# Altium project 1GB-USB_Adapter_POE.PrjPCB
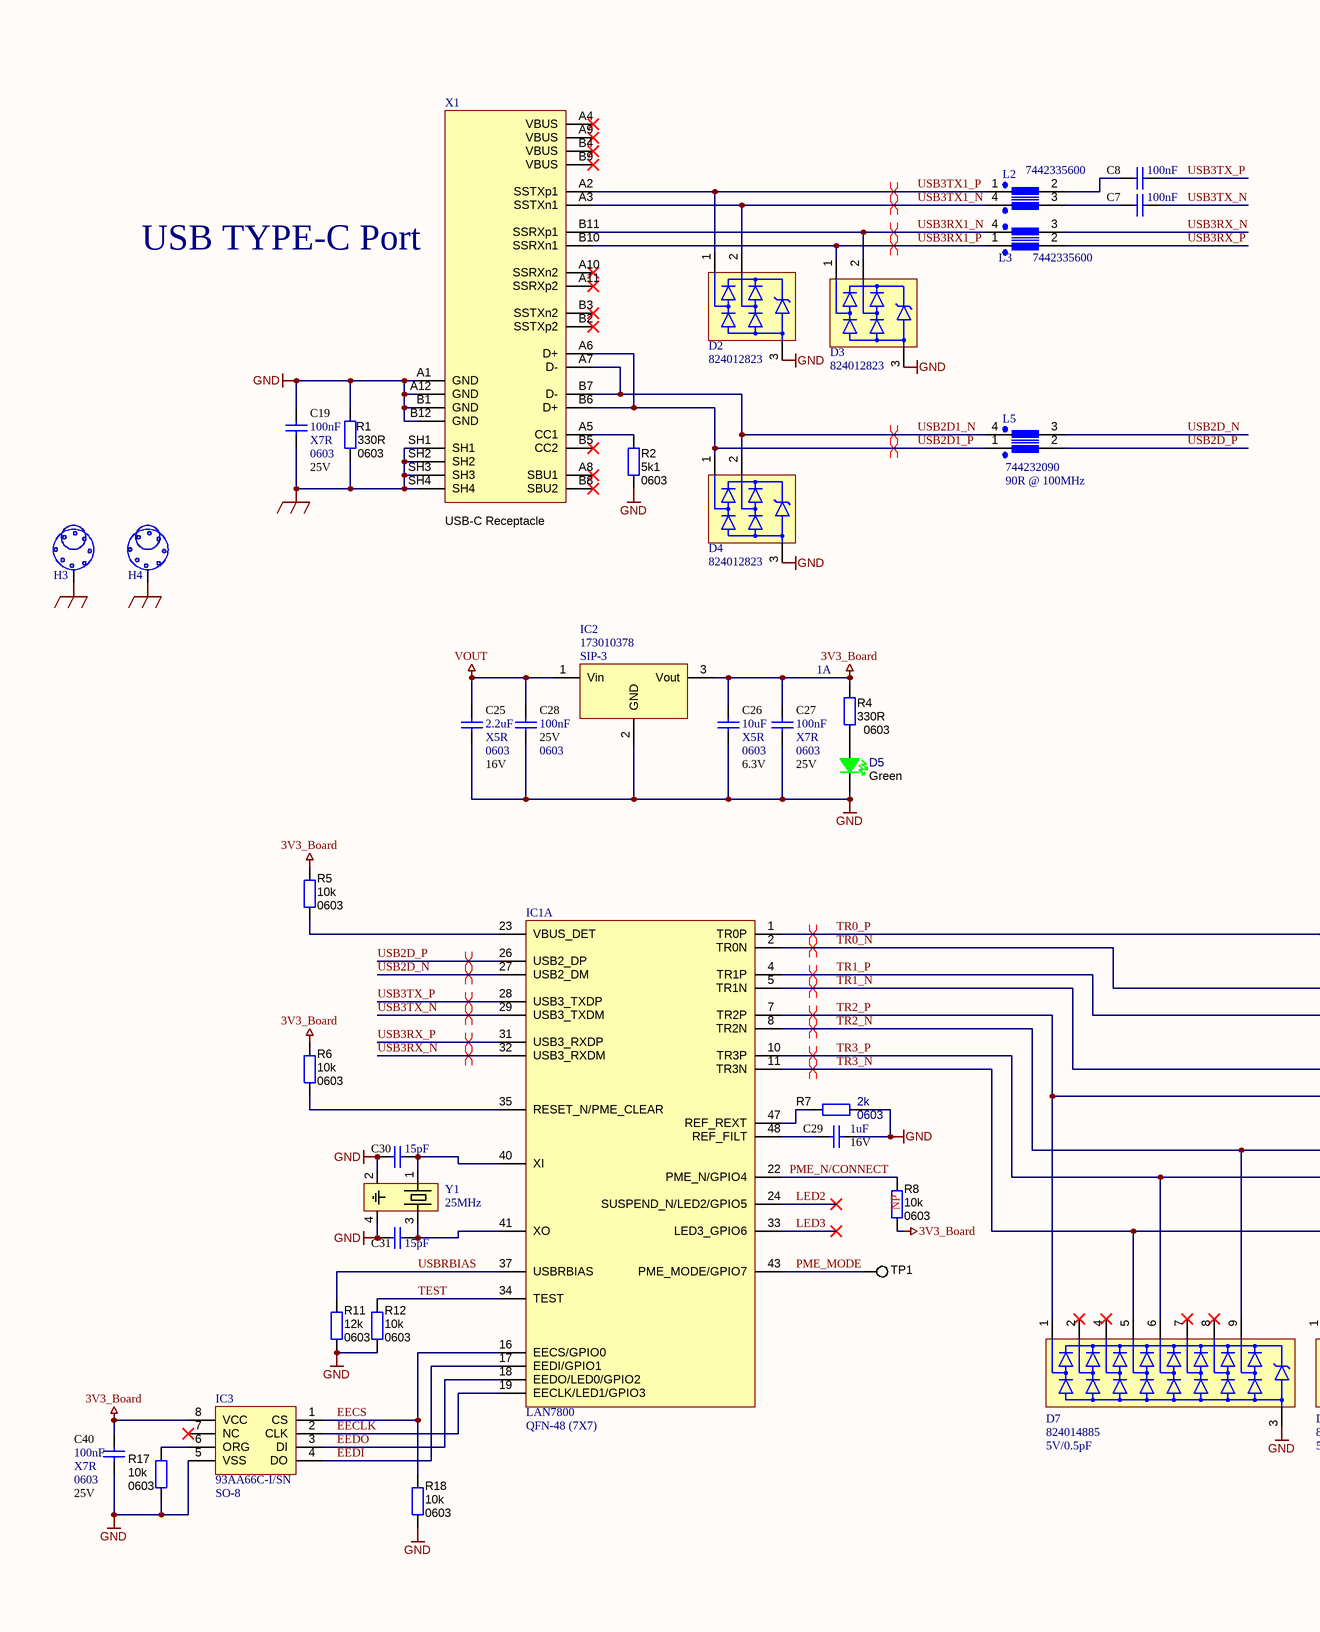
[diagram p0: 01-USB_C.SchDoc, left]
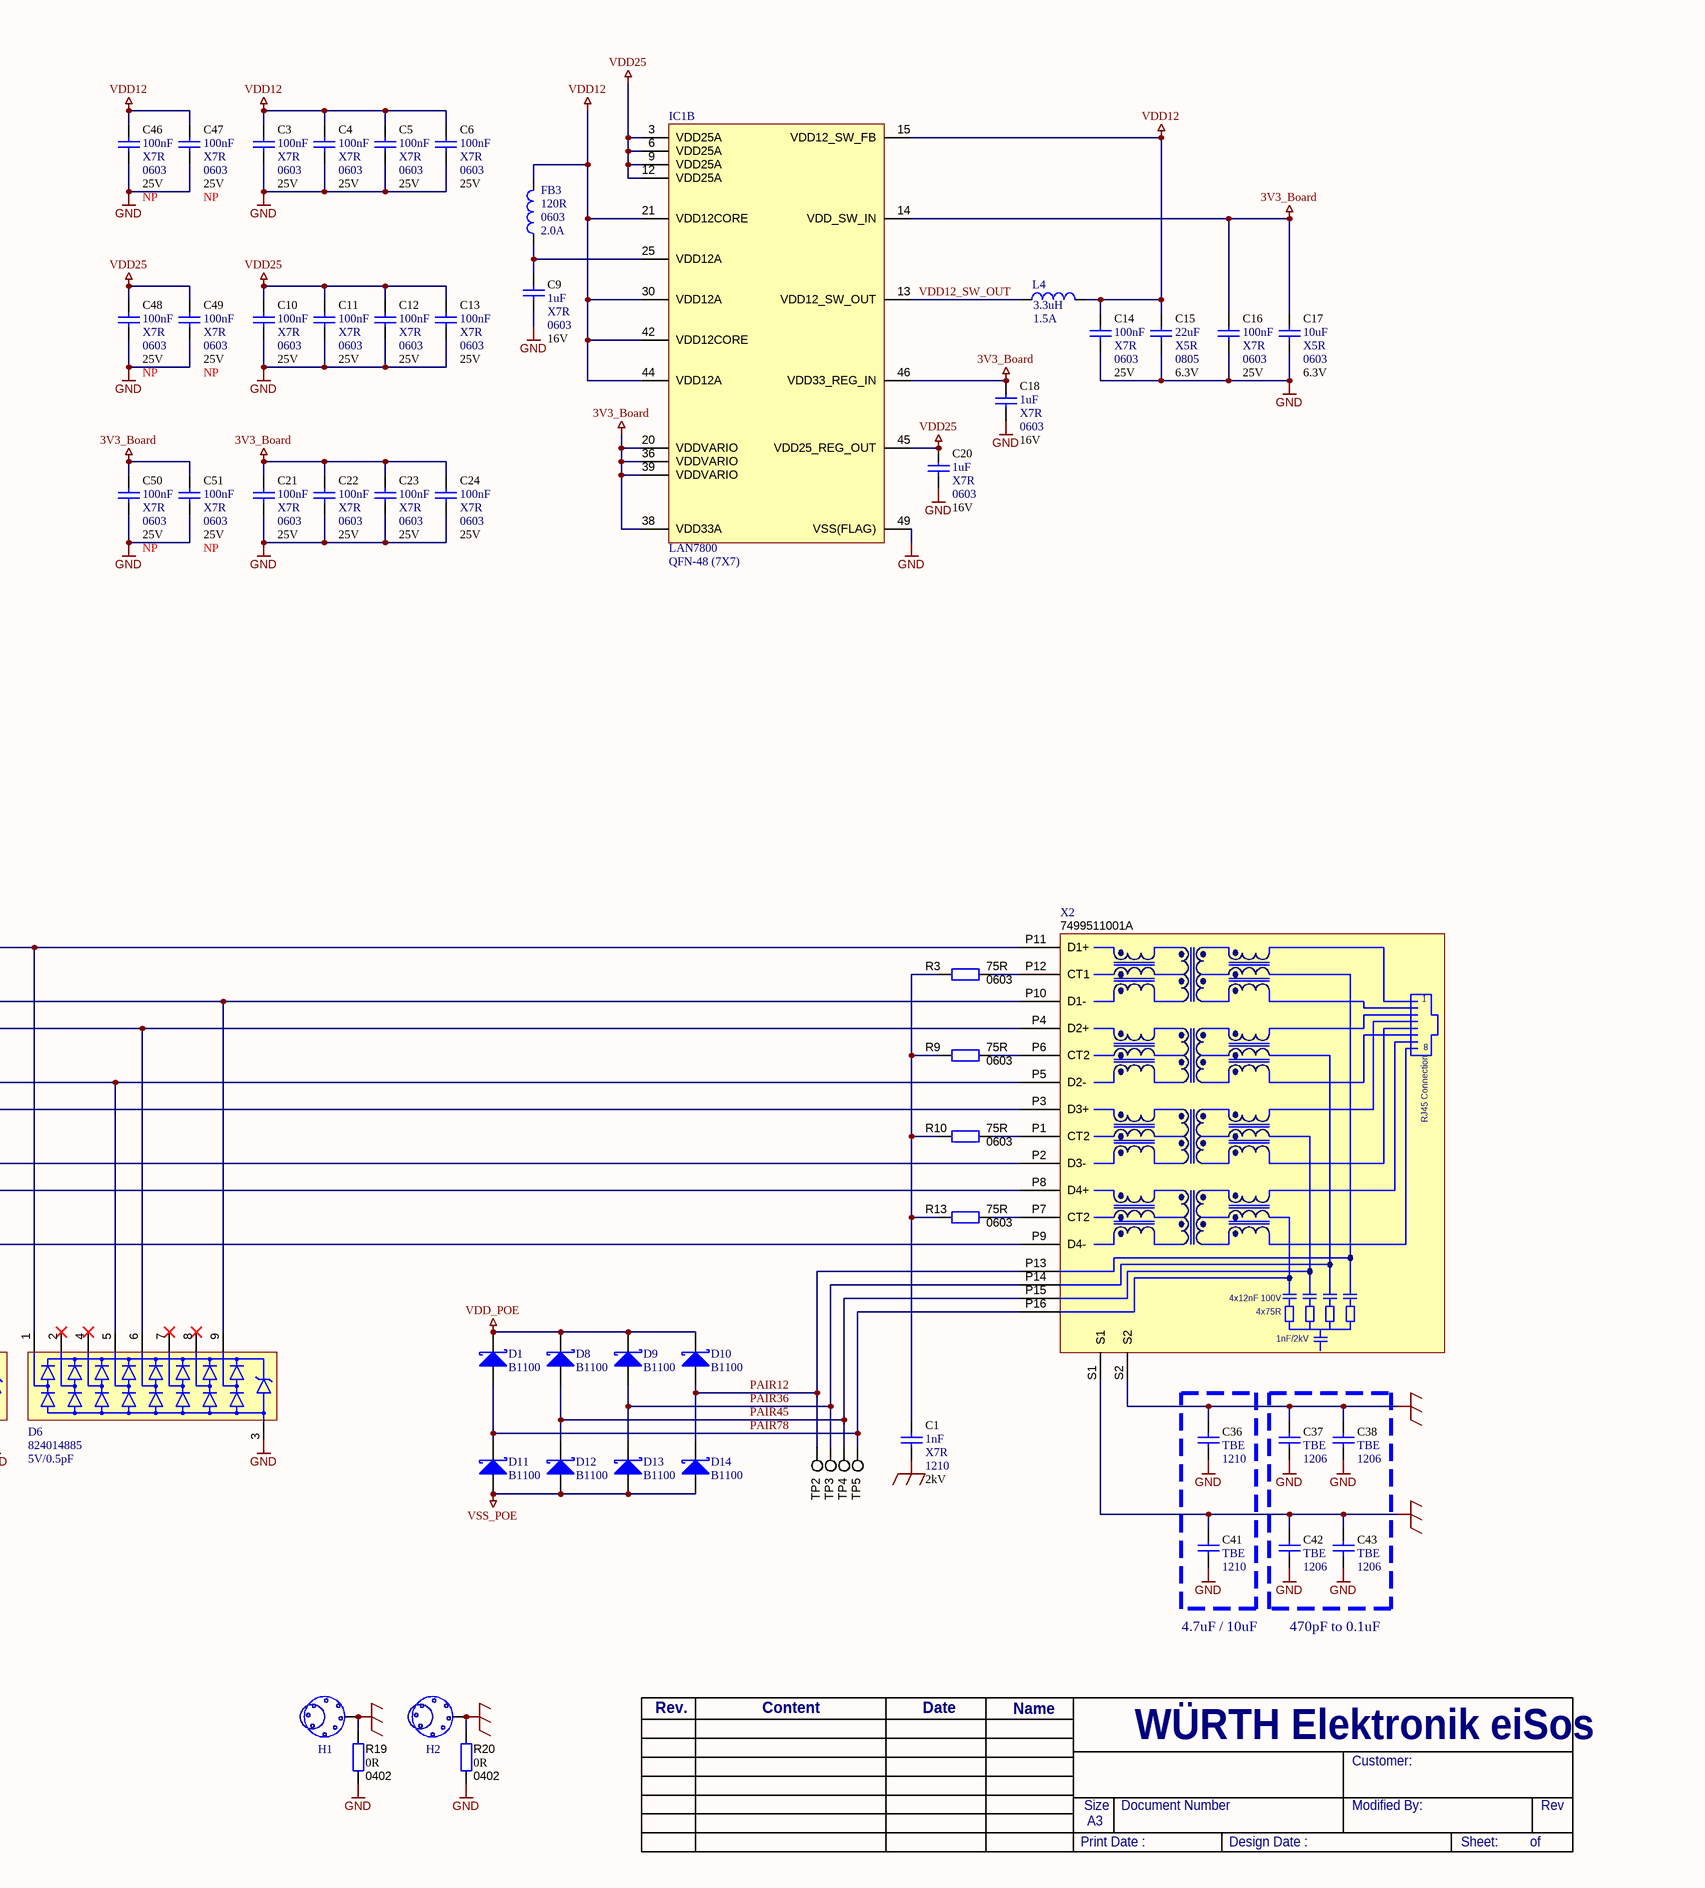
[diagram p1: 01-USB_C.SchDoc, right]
2 sheets, 189 parts. Net scope: global (net labels, ports and power ports of the same name join across sheets).
Board file: 1GB-USB_Adapter_POE_ V13.PcbDoc
Sheets:
  01-USB_C.SchDoc
  02-POE.SchDoc

## Sheet 01-USB_C.SchDoc: Ethernet and USB-C ports
size A2; Date: Sun 31th Oct, 2021; CompanyName: RGT Supply and Service Ltd.; Engineer: Nattawut; Address1: 285/95 M.3 T.Tonpao A.Sankumphaeng; Address2: Thailand 50130 Thailand Tel.+66 89 1645339; Revision: 1.3; SheetNumber: 1; SheetTotal: 2; ContentRev1: Original Document; dateREV1: 31-10-2021; NameRev1: Nattawut; NameRev3: Nattawut; NameRev2: Nattawut; NameRev4: Nattawut; dateREV2: 02-10-2022; dateREV3: 10-02-2023; dateREV4: 04-03-2023; ContentRev2: Remove Net SSRX2, SSTX2; ContentRev3: Improve for EMC; ContentRev4: Update C2, C25; Rev1: 1.0; Rev2: 1.1; Rev3: 1.2; Rev4: 1.3; Project: 1GB_USB Adapter with PoE; PageSetup: Record=PageOptions¦CenterHorizontal=True¦CenterVertical=True¦PrintScale=0.73¦XCorrection=1.00¦YCorrection=1.00¦PrintKind=0¦BorderSize=5000000¦LeftOffset=0¦BottomOffset=0¦Orientation=2¦PaperLength=1000¦PaperWidth=1000¦Scale=100¦PaperSource=7¦PrintQuality=-3¦MediaType=1¦DitherType=10¦PrintScaleMode=1¦PaperKind=A3¦PaperIndex=8

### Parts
C1  value 1nF  VDC_V: 2kV  PackageReference: 1210  Dielectric: X7R  [CC3225-1210]  (hidden comment: 885342209009)
C3  value 100nF  VDC_V: 25V  PackageReference: 0603  Dielectric: X7R  [CC1608-0603]  (hidden comment: 885012206071)
C4  value 100nF  VDC_V: 25V  PackageReference: 0603  Dielectric: X7R  [CC1608-0603]  (hidden comment: 885012206071)
C5  value 100nF  VDC_V: 25V  PackageReference: 0603  Dielectric: X7R  [CC1608-0603]  (hidden comment: 885012206071)
C6  value 100nF  VDC_V: 25V  PackageReference: 0603  Dielectric: X7R  [CC1608-0603]  (hidden comment: 885012206071)
C7  value 100nF  [CC1005-0402]  (hidden comment: 885012105018)
C8  value 100nF  [CC1005-0402]  (hidden comment: 885012105018)
C9  value 1uF  VDC_V: 16V  PackageReference: 0603  Dielectric: X7R  [CC1608-0603]  (hidden comment: 885012206052)
C10  value 100nF  VDC_V: 25V  PackageReference: 0603  Dielectric: X7R  [CC1608-0603]  (hidden comment: 885012206071)
C11  value 100nF  VDC_V: 25V  PackageReference: 0603  Dielectric: X7R  [CC1608-0603]  (hidden comment: 885012206071)
C12  value 100nF  VDC_V: 25V  PackageReference: 0603  Dielectric: X7R  [CC1608-0603]  (hidden comment: 885012206071)
C13  value 100nF  VDC_V: 25V  PackageReference: 0603  Dielectric: X7R  [CC1608-0603]  (hidden comment: 885012206071)
C14  value 100nF  VDC_V: 25V  PackageReference: 0603  Dielectric: X7R  [CC1608-0603]  (hidden comment: 885012206071)
C15  value 22uF  VDC_V: 6.3V  PackageReference: 0805  Dielectric: X5R  [CC2012-0805]  (hidden comment: 885012107005)
C16  value 100nF  VDC_V: 25V  PackageReference: 0603  Dielectric: X7R  [CC1608-0603]  (hidden comment: 885012206071)
C17  value 10uF  VDC_V: 6.3V  PackageReference: 0603  Dielectric: X5R  [CC1608-0603]  (hidden comment: 885012106006)
C18  value 1uF  VDC_V: 16V  PackageReference: 0603  Dielectric: X7R  [CC1608-0603]  (hidden comment: 885012206052)
C19  value 100nF  VDC_V: 25V  PackageReference: 0603  Dielectric: X7R  [CC1608-0603]  (hidden comment: 885012206071)
C20  value 1uF  VDC_V: 16V  PackageReference: 0603  Dielectric: X7R  [CC1608-0603]  (hidden comment: 885012206052)
C21  value 100nF  VDC_V: 25V  PackageReference: 0603  Dielectric: X7R  [CC1608-0603]  (hidden comment: 885012206071)
C22  value 100nF  VDC_V: 25V  PackageReference: 0603  Dielectric: X7R  [CC1608-0603]  (hidden comment: 885012206071)
C23  value 100nF  VDC_V: 25V  PackageReference: 0603  Dielectric: X7R  [CC1608-0603]  (hidden comment: 885012206071)
C24  value 100nF  VDC_V: 25V  PackageReference: 0603  Dielectric: X7R  [CC1608-0603]  (hidden comment: 885012206071)
C25  value 2.2uF  VDC_V: 16V  PackageReference: 0603  Dielectric: X5R  [CC1608-0603]  (hidden comment: 885012106018)
C26  value 10uF  VDC_V: 6.3V  PackageReference: 0603  Dielectric: X5R  [CC1608-0603]  (hidden comment: 885012106006)
C27  value 100nF  VDC_V: 25V  PackageReference: 0603  Dielectric: X7R  [CC1608-0603]  (hidden comment: 885012206071)
C28  value 100nF  VDC_V: 25V  PackageReference: 0603  [CC1608-0603]  (hidden comment: 885012206071)
C29  value 1uF  VDC_V: 16V  [CC1608-0603]  (hidden comment: 885012206052)
C30  value 15pF  [CC1005-0402]  (hidden comment: 885012005056)
C31  value 15pF  [CC1005-0402]  (hidden comment: 885012005056)
C36  value TBE  PackageReference: 1210  [CC3225-1210]
C37  value TBE  PackageReference: 1206  [CC3216-1206]
C38  value TBE  PackageReference: 1206  [CC3216-1206]
C40  value 100nF  VDC_V: 25V  PackageReference: 0603  Dielectric: X7R  [CC1608-0603]  (hidden comment: 885012206071)
C41  value TBE  PackageReference: 1210  [CC3225-1210]
C42  value TBE  PackageReference: 1206  [CC3216-1206]
C43  value TBE  PackageReference: 1206  [CC3216-1206]
C46  value 100nF  VDC_V: 25V  PackageReference: 0603  Dielectric: X7R  Populated: NP  [CC1608-0603]  (hidden comment: 885012206071)
C47  value 100nF  VDC_V: 25V  PackageReference: 0603  Dielectric: X7R  Populated: NP  [CC1608-0603]  (hidden comment: 885012206071)
C48  value 100nF  VDC_V: 25V  PackageReference: 0603  Dielectric: X7R  Populated: NP  [CC1608-0603]  (hidden comment: 885012206071)
C49  value 100nF  VDC_V: 25V  PackageReference: 0603  Dielectric: X7R  Populated: NP  [CC1608-0603]  (hidden comment: 885012206071)
C50  value 100nF  VDC_V: 25V  PackageReference: 0603  Dielectric: X7R  Populated: NP  [CC1608-0603]  (hidden comment: 885012206071)
C51  value 100nF  VDC_V: 25V  PackageReference: 0603  Dielectric: X7R  Populated: NP  [CC1608-0603]  (hidden comment: 885012206071)
D1  value B1100  [SMA/DO-214AC]  (hidden comment: B1100-13-F)
D2  824012823  [DFN1210-6L 1.2X1.0]
D3  824012823  [DFN1210-6L 1.2X1.0]
D4  824012823  [DFN1210-6L 1.2X1.0]
D5  value Green  [LED1608 (0603) - Green]  (hidden comment: 150060VS75020)
D6  Voltage: 5V/0.5pF  [WE-TVS_824014885]  (hidden comment: 824014885)
D7  Voltage: 5V/0.5pF  [WE-TVS_824014885]  (hidden comment: 824014885)
D8  value B1100  [SMA/DO-214AC]  (hidden comment: B1100-13-F)
D9  value B1100  [SMA/DO-214AC]  (hidden comment: B1100-13-F)
D10  value B1100  [SMA/DO-214AC]  (hidden comment: B1100-13-F)
D11  value B1100  [SMA/DO-214AC]  (hidden comment: B1100-13-F)
D12  value B1100  [SMA/DO-214AC]  (hidden comment: B1100-13-F)
D13  value B1100  [SMA/DO-214AC]  (hidden comment: B1100-13-F)
D14  value B1100  [SMA/DO-214AC]  (hidden comment: B1100-13-F)
FB3  value 120R  PackageReference: 0603  I DC: 2.0A  [CF1608-0603]  (hidden comment: 742792625)
H1  Hole M3 with Vias  [M3_VIA]  (value not drawn)
H2  Hole M3 with Vias  [M3_VIA]  (value not drawn)
H3  Hole M3 with Vias  [M3_VIA]  (value not drawn)
H4  Hole M3 with Vias  [M3_VIA]  (value not drawn)
IC1  value LAN7800  PackageReference: QFN-48 (7X7)  [QFN-48 7x7MM]  (hidden comment: LAN7800/Y9X)  (parts A,B of 2)
IC2  PackageReference: SIP-3  [WE_SIP-3]  (hidden comment: 173010378)
IC3  PackageReference: SO-8  [SO-8N]  (hidden comment: 93AA66C-I/SN)
L2  7442335600  [INDUCTOR_WE-CNSW-HF-0504]
L3  7442335600  [INDUCTOR_WE-CNSW-HF-0504]
L4  value 3.3uH  I DC: 1.5A  [Inductor_WE-LQS 3015]  (hidden comment: 74404032033)
L5  value 90R @ 100MHz  [INDUCTOR_WE-CNSW-1206]  (hidden comment: 744232090)
R1  value 330R  PackageReference: 0603  [CR1608-0603]  (hidden comment: RC0603FR-07330RL)
R2  value 5k1  PackageReference: 0603  [CR1608-0603]  (hidden comment: RC0603FR-075K1L)
R3  value 75R  PackageReference: 0603  [CR1608-0603]  (hidden comment: RC0603FR-0775RL)
R4  value 330R  PackageReference: 0603  [CR1608-0603]  (hidden comment: RC0603FR-07330RL)
R5  value 10k  PackageReference: 0603  [CR1608-0603]  (hidden comment: RC0603FR-0710KL)
R6  value 10k  PackageReference: 0603  [CR1608-0603]  (hidden comment: RC0603FR-0710KL)
R7  value 2k  PackageReference: 0603  [CR1608-0603]  (hidden comment: RC0603FR-072KL)
R8  value 10k  PackageReference: 0603  Populated: NP  [CR1608-0603]  (hidden comment: RC0603FR-0710KL)
R9  value 75R  PackageReference: 0603  [CR1608-0603]  (hidden comment: RC0603FR-0775RL)
R10  value 75R  PackageReference: 0603  [CR1608-0603]  (hidden comment: RC0603FR-0775RL)
R11  value 12k  PackageReference: 0603  [CR1608-0603]  (hidden comment: RC0603FR-0712KL)
R12  value 10k  PackageReference: 0603  [CR1608-0603]  (hidden comment: RC0603FR-0710KL)
R13  value 75R  PackageReference: 0603  [CR1608-0603]  (hidden comment: RC0603FR-0775RL)
R17  value 10k  PackageReference: 0603  [CR1608-0603]  (hidden comment: RC0603FR-0710KL)
R18  value 10k  PackageReference: 0603  [CR1608-0603]  (hidden comment: RC0603FR-0710KL)
R19  value 0R  PackageReference: 0402  [CR1005-0402]  (hidden comment: RC0402FR-070RL)
R20  value 0R  PackageReference: 0402  [CR1005-0402]  (hidden comment: RC0402FR-070RL)
TP1  (no value)  [TESTPOINT 1.5mm]
TP2  (no value)  [TESTPOINT 1.5mm]
TP3  (no value)  [TESTPOINT 1.5mm]
TP4  (no value)  [TESTPOINT 1.5mm]
TP5  (no value)  [TESTPOINT 1.5mm]
X1  value USB-C Receptacle  [632723300011_USB_TypeC]  (hidden comment: 632723300011)
X2  7499511001A  [RJ45_7499511001A]
Y1  value 25MHz  [CRYSTAL_3225]  (hidden comment: 830055299)

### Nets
3V3_Board: C16.1 C17.2 C18.1 C21.1 C22.1 C23.1 C24.1 C26.2 C27.1 C40.1 C50.1 C51.1 IC1.14(VDD_SW_IN) IC1.20(VDDVARIO) IC1.36(VDDVARIO) IC1.38(VDD33A) IC1.39(VDDVARIO) IC1.46(VDD33_REG_IN) IC2.3(Vout) IC3.8(VCC) R4.1 R5.1 R6.1 R8.2
GND: C3.2 C4.2 C5.2 C6.2 C9.2 C10.2 C11.2 C12.2 C13.2 C14.2 C15.1 C16.2 C17.1 C18.2 C19.1 C20.2 C21.2 C22.2 C23.2 C24.2 C25.1 C26.1 C27.2 C28.2 C29.2 C30.1 C31.1 C36.2 C37.2 C38.2 C40.2 C41.2 C42.2 C43.2 C46.2 C47.2 C48.2 C49.2 C50.2 C51.2 D2.3(GND) D3.3(GND) D4.3(GND) D5.1 D6.3(GND) D7.3(GND) IC1.49(VSS(FLAG)) IC2.2(GND) IC3.5(VSS) R1.1 R2.2 R7.2 R11.2 R12.2 R17.2 R18.2 R19.2 R20.2 X1.A1(GND) X1.A12(GND) X1.B1(GND) X1.B12(GND) Y1.2 Y1.4
SHIELD: C1.2 C19.2 C36.1 C37.1 C38.1 C41.1 C42.1 C43.1 H1.0(Hole) H2.0(Hole) H3.0(Hole) H4.0(Hole) R1.2 R19.1 R20.1 X1.SH1 X1.SH2 X1.SH3 X1.SH4 X2.S1 X2.S2
VDD12: C3.1 C4.1 C5.1 C6.1 C14.1 C15.2 C46.1 C47.1 FB3.2 IC1.15(VDD12_SW_FB) IC1.21(VDD12CORE) IC1.30(VDD12A) IC1.42(VDD12CORE) IC1.44(VDD12A) L4.2
VDD25: C10.1 C11.1 C12.1 C13.1 C20.1 C48.1 C49.1 IC1.3(VDD25A) IC1.6(VDD25A) IC1.9(VDD25A) IC1.12(VDD25A) IC1.45(VDD25_REG_OUT)
VDD_POE: D1.2(K) D8.2(K) D9.2(K) D10.2(K)
VOUT: C25.2 C28.1 IC2.1(Vin)
VSS_POE: D11.1(A) D12.1(A) D13.1(A) D14.1(A)
EECLK: IC1.19(EECLK/LED1/GPIO3) IC3.2(CLK)
EECS: IC1.16(EECS/GPIO0) IC3.1(CS) R18.1
EEDI: IC1.17(EEDI/GPIO1) IC3.4(DO)
EEDO: IC1.18(EEDO/LED0/GPIO2) IC3.3(DI)
LED2: IC1.24(SUSPEND_N/LED2/GPIO5)
LED3: IC1.33(LED3_GPIO6)
PAIR12: D10.1(A) D14.2(K) TP2.1 X2.P13
PAIR36: D9.1(A) D13.2(K) TP3.1 X2.P14
PAIR45: D8.1(A) D12.2(K) TP4.1 X2.P15
PAIR78: D1.1(A) D11.2(K) TP5.1 X2.P16
PME_MODE: IC1.43(PME_MODE/GPIO7) TP1.1
PME_N/CONNECT: IC1.22(PME_N/GPIO4) R8.1
TEST: IC1.34(TEST) R12.1
TR0_N: D6.9(IO8) IC1.2(TR0N) X2.P10(D1-)
TR0_P: D6.1(IO1) IC1.1(TR0P) X2.P11(D1+)
TR1_N: D6.5(IO4) IC1.5(TR1N) X2.P5(D2-)
TR1_P: D6.6(IO5) IC1.4(TR1P) X2.P4(D2+)
TR2_N: D7.9(IO8) IC1.8(TR2N) X2.P2(D3-)
TR2_P: D7.1(IO1) IC1.7(TR2P) X2.P3(D3+)
TR3_N: D7.5(IO4) IC1.11(TR3N) X2.P9(D4-)
TR3_P: D7.6(IO5) IC1.10(TR3P) X2.P8(D4+)
USB2D1_N: D4.2(IO2) L5.4(Pri2) X1.A7(D-) X1.B7(D-)
USB2D1_P: D4.1(IO1) L5.1(Pri1) X1.A6(D+) X1.B6(D+)
USB2D_N: IC1.27(USB2_DM) L5.3(Sec2)
USB2D_P: IC1.26(USB2_DP) L5.2(Sec1)
USB3RX1_N: D3.2(IO2) L3.4(Pri2) X1.B11(SSRXp1)
USB3RX1_P: D3.1(IO1) L3.1(Pri1) X1.B10(SSRXn1)
USB3RX_N: IC1.32(USB3_RXDM) L3.3(Sec2)
USB3RX_P: IC1.31(USB3_RXDP) L3.2(Sec1)
USB3TX1_N: D2.2(IO2) L2.4(Pri2) X1.A3(SSTXn1)
USB3TX1_P: D2.1(IO1) L2.1(Pri1) X1.A2(SSTXp1)
USB3TX_N: C7.2 IC1.29(USB3_TXDM)
USB3TX_P: C8.2 IC1.28(USB3_TXDP)
USBRBIAS: IC1.37(USBRBIAS) R11.1
VDD12_SW_OUT: IC1.13(VDD12_SW_OUT) L4.1
NetC1_1: C1.1 R3.2 R9.2 R10.2 R13.2
NetC7_1: C7.1 L2.3(Sec2)
NetC8_1: C8.1 L2.2(Sec1)
NetC9_1: C9.1 FB3.1 IC1.25(VDD12A)
NetC29_1: C29.1 IC1.48(REF_FILT)
NetC30_2: C30.2 IC1.40(XI) Y1.1
NetC31_2: C31.2 IC1.41(XO) Y1.3
NetD5_2: D5.2 R4.2
NetIC1_23: IC1.23(VBUS_DET) R5.2
NetIC1_35: IC1.35(RESET_N/PME_CLEAR) R6.2
NetIC1_47: IC1.47(REF_REXT) R7.1
NetIC3_6: IC3.6(ORG) R17.1
NetR2_1: R2.1 X1.A5(CC1)
NetR3_1: R3.1 X2.P12(CT1)
NetR9_1: R9.1 X2.P6(CT2)
NetR10_1: R10.1 X2.P1(CT2)
NetR13_1: R13.1 X2.P7(CT2)

Not connected (* = marked no-connect by the designer): D6 2(IO2)* 4(IO3)* 7(IO6)* 8(IO7)*; D7 2(IO2)* 4(IO3)* 7(IO6)* 8(IO7)*; IC3 7(NC)*; X1 A4(VBUS)* A8(SBU1)* A9(VBUS)* A10(SSRXn2)* A11(SSRXp2)* B2(SSTXp2)* B3(SSTXn2)* B4(VBUS)* B5(CC2)* B8(SBU2)* B9(VBUS)*

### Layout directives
differential pair: TR0_N, TR0_P, TR1_N, TR1_P, TR2_N, TR2_P, TR3_N, TR3_P, USB2D1_N, USB2D1_P, USB2D_N, USB2D_P, USB3RX1_N, USB3RX1_P, USB3RX_N, USB3RX_P, USB3TX1_N, USB3TX1_P, USB3TX_N, USB3TX_P

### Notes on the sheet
- (near X1) USB TYPE-C Port
- (near R4) 1A
- 4.7uF / 10uF
- 470pF to 0.1uF
- Rev.
- Content
- Date
- Name
- WÜRTH Elektronik eiSos
- Customer:
- Print Date :
- Size
- A3
- Document Number
- Design Date :
- Modified By:
- Sheet:
- of
- Rev

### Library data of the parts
C1 = 885342209009: CAP, CERM, 1nF, 2kV, +/-10%, X7R, 1210; Manufacturer: Wurth; Polarized: N; TaMax_C: 125; TaMin_C: -55; Tolerance_%: 10%; CompType: Capacitor
C3-C6 C10-C14 C16 C19 C21-C24 C27 C28 C40 C46-C51 = 885012206071: CAP, CERM, 100nF, 25V, +/-10%, X7R, 0603; Manufacturer: Wurth; Polarized: N; TaMax_C: 125; TaMin_C: -55; Tolerance_%: 10; CompType: Capacitor
C7 C8 = 885012105018: CAP, CERM, 100nF, 25V, +/-20%, X5R, 0402; Manufacturer: Wurth; Polarized: N; TaMax_C: 85; TaMin_C: -55; Tolerance_%: 20; CompType: Capacitor
C9 C18 C20 C29 = 885012206052: CAP, CERM, 1uF, 16V, +/-10%, X7R, 0603; Manufacturer: Wurth; Polarized: N; TaMax_C: 125; TaMin_C: -55; Tolerance_%: 10%; CompType: Capacitor
C15 = 885012107005: CAP, CERM, 22uF, 6.3V, +/-20%, X5R, 0805; Manufacturer: Wurth; Polarized: N; TaMax_C: 85; TaMin_C: -55; Tolerance_%: 20; CompType: Capacitor
C17 C26 = 885012106006: CAP, CERM, 10uF, 6.3V, +/-20%, X5R, 0603; Manufacturer: Wurth; Polarized: N; TaMax_C: 85; TaMin_C: -55; Tolerance_%: 10; CompType: Capacitor
C25 = 885012106018: CAP, CERM, 2.2uF, 16V, +/-20%, X5R, 0603; Manufacturer: Wurth; Polarized: N; TaMax_C: 85; TaMin_C: -55; Tolerance_%: 20%; CompType: Capacitor
C30 C31 = 885012005056: CAP, CERM, 15pF, 50V, +/-5%, C0G, 0402; Manufacturer: Wurth; Polarized: N; TaMax_C: 125; TaMin_C: -55; Tolerance_%: 5; CompType: Capacitor
C36 C41 = TBE_CAP_1210: CAP, CERM, TBE, 1210; Polarized: N; TaMax_C: 125; TaMin_C: -55; CompType: Capacitor
C37 C38 C42 C43 = TBE_CAP_1206: CAP, CERM, TBE, 1206; Polarized: N; TaMax_C: 125; TaMin_C: -55; CompType: Capacitor
D1 D8-D14 = B1100-13-F: DIODE, Schottky, 100V, 1A, SMA; Manufacturer: Diodes
D2-D4 = 824012823: DIODE, TVS Super Speed , 3.3V, DFN1210-6L; Manufacturer: Wurth
D5 = 150060VS75020: LED 572NM GREEN 0603 SMD; Manufacturer: Wurth
D6 D7 = 824014885: DIODE, TVS Super Speed , 5V, 8CH, 3.8x1.0mm; Manufacturer: Wurth
FB3 = 742792625: Ferrite Bead 120R @ 100MHz / 0603 / 2.0A; Manufacturer: Wurth
H1-H4 = Hole M3 with Vias: SAP: xxxx
IC1 = LAN7800/Y9X: IC USB3.1 to 1G Ethernet Bridge, 3.3V, QFN-48; Manufacturer: Microchip
IC2 = 173010378: DC/DC Converters, Non-Isolated, 7-28Vin, 3.3Vout, 3.3W; Manufacturer: Wurth
IC3 = 93AA66C-I/SN: IC EEPROM, SPI, 4kb, 16MHz, 1.8-5.5V, SO-8; Manufacturer: Microchip
L2 L3 = 7442335600: Common Mode Chokes 60R @ 100MHz / 1x1.2mm / 600mA; Manufacturer: Wurth; I DC: 0.6A
L4 = 74404032033: Inductor 3.3uH / 3015 / 1.5A; Manufacturer: Wurth
L5 = 744232090: Common Mode Chokes 90R @ 100MHz / 1206 / 370mA; Manufacturer: Wurth; I DC: 0.37A
R1 R4 = RC0603FR-07330RL: RES, 330 ohm, 1%, 0.1W, 0603; Manufacturer: Yageo; CompType: Resistor; Power_W: 0.1
R2 = RC0603FR-075K1L: RES, 5.1kohm, 1%, 0.1W, 0603; Manufacturer: Yageo; CompType: Resistor; Power_W: 0.1
R3 R9 R10 R13 = RC0603FR-0775RL: RES, 75 ohm, 1%, 0.1W, 0603; Manufacturer: Yageo; CompType: Resistor; Power_W: 0.1
R5 R6 R8 R12 R17 R18 = RC0603FR-0710KL: RES, 10kohm, 1%, 0.1W, 0603; Manufacturer: Yageo; CompType: Resistor; Power_W: 0.1
R7 = RC0603FR-072KL: RES, 2kohm, 1%, 0.1W, 0603; Manufacturer: Yageo; CompType: Resistor; Power_W: 0.1
R11 = RC0603FR-0712KL: RES, 12kohm, 1%, 0.1W, 0603; Manufacturer: Yageo; CompType: Resistor; Power_W: 0.1
R19 R20 = RC0402FR-070RL: RES, 0 ohm, 1%, 0.063W, 0402; Manufacturer: Yageo; CompType: Resistor; Power_W: 0.063
TP1-TP5 = TP / 1.5mm: Test Point, SMT, Miniature; Value: 1.5mm
X1 = 632723300011: CON, USB, Type C, Female, 24P, Hor, SMT; Manufacturer: Wurth; CompType: Connector
X2 = 7499511001A: CON, Ethernet, Int Magnetics, POE+, 8P, 1x1 Tab-Up, INS; Manufacturer: Wurth; CompType: Connector
Y1 = 830055299: Crystal / 25MHz / 18pF / 30ppm; Manufacturer: Wurth

## Sheet 02-POE.SchDoc: POE
size A2; Date: Sun 31th Oct, 2021; CompanyName: RGT Supply and Service Ltd.; Engineer: Nattawut; Address1: 285/95 M.3 T.Tonpao A.Sankumphaeng; Address2: Thailand 50130 Thailand Tel.+66 89 1645339; Revision: 1.3; SheetNumber: 2; SheetTotal: 2; ContentRev1: Original Document; dateREV1: 31-10-2021; NameRev1: Nattawut; NameRev3: Nattawut; NameRev2: Nattawut; NameRev4: Nattawut; dateREV2: 02-10-2022; dateREV3: 10-02-2023; dateREV4: 04-03-2023; ContentRev2: Remove Net SSRX2, SSTX2; ContentRev3: Improve for EMC; ContentRev4: Update C2, C25; Rev1: 1.0; Rev2: 1.1; Rev3: 1.2; Rev4: 1.3; Project: 1GB_USB Adapter with PoE; PageSetup: Record=PageOptions¦CenterHorizontal=True¦CenterVertical=True¦PrintScale=0.73¦XCorrection=1.00¦YCorrection=1.00¦PrintKind=0¦BorderSize=5000000¦LeftOffset=0¦BottomOffset=0¦Orientation=2¦PaperLength=1000¦PaperWidth=1000¦Scale=100¦PaperSource=7¦PrintQuality=-3¦MediaType=1¦DitherType=10¦PrintScaleMode=1¦PaperKind=A3¦PaperIndex=8
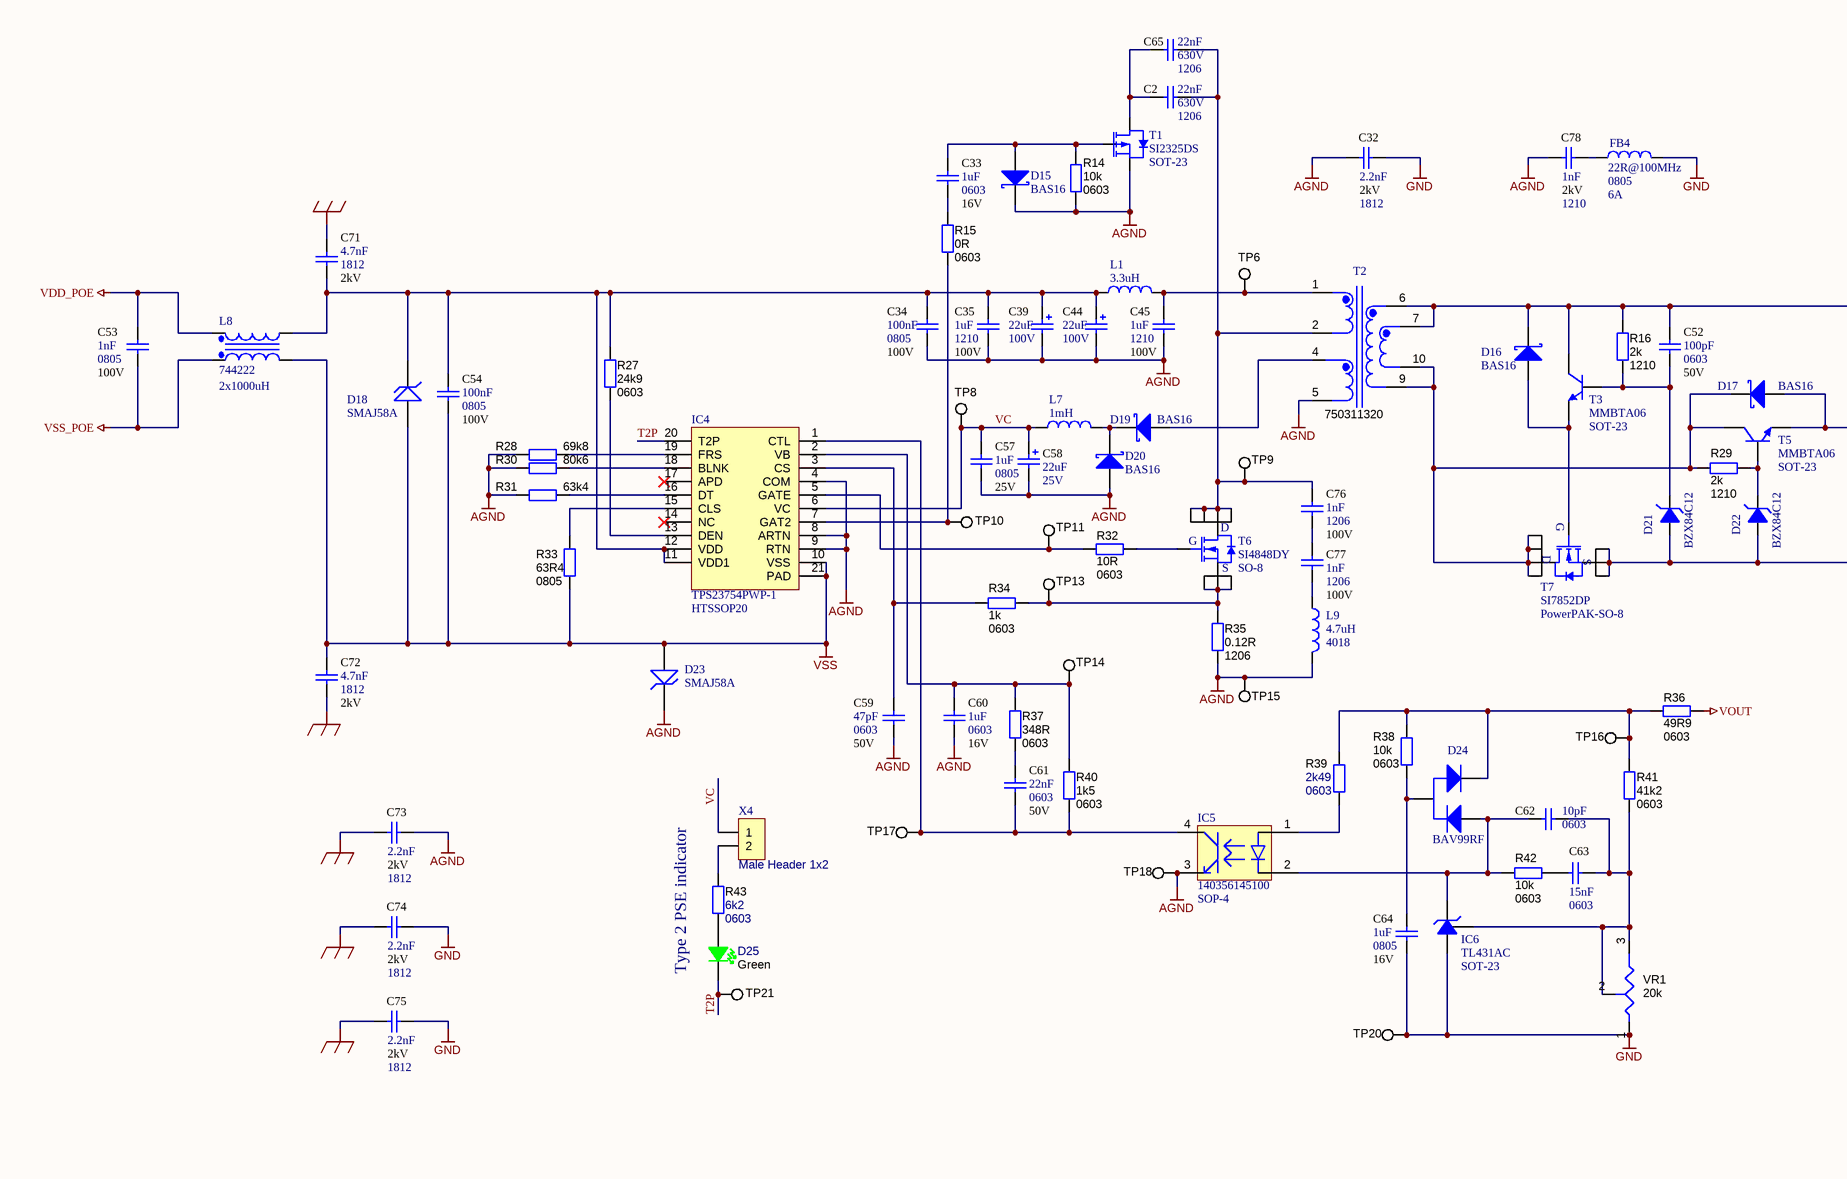
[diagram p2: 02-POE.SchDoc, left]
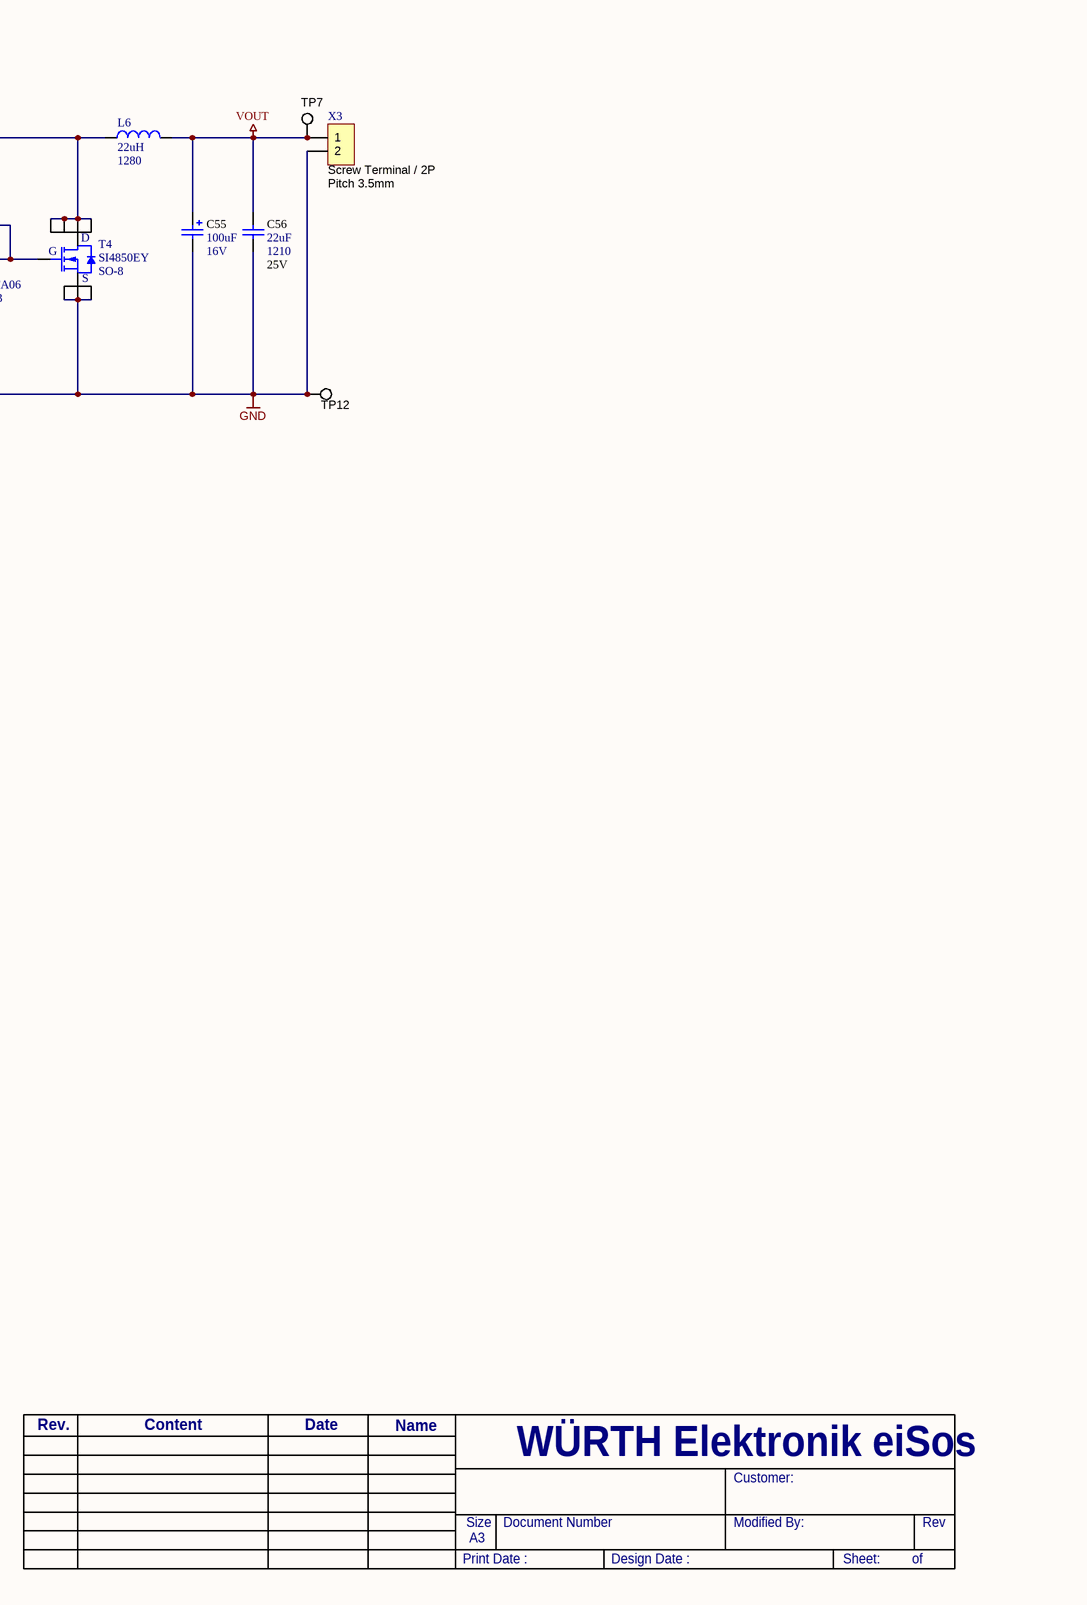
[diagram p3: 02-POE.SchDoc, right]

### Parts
C2  value 22nF  PackageReference: 1206  VDC_V: 630V  [CC3216-1206]  (hidden comment: 885342208014)
C32  value 2.2nF  VDC_V: 2kV  PackageReference: 1812  [CC4532-1812]  (hidden comment: 885342210002)
C33  value 1uF  VDC_V: 16V  PackageReference: 0603  [CC1608-0603]  (hidden comment: 885012206052)
C34  value 100nF  VDC_V: 100V  PackageReference: 0805  [CC2012-0805]  (hidden comment: 885012207128)
C35  value 1uF  VDC_V: 100V  PackageReference: 1210  [CC3225-1210]  (hidden comment: 885012209069)
C39  value 22uF  VDC_V: 100V  [SMT 8mmx10mm - WE]  (hidden comment: 865080853006)
C44  value 22uF  VDC_V: 100V  [SMT 8mmx10mm - WE]  (hidden comment: 865080853006)
C45  value 1uF  VDC_V: 100V  PackageReference: 1210  [CC3225-1210]  (hidden comment: 885012209069)
C52  value 100pF  VDC_V: 50V  PackageReference: 0603  [CC1608-0603]  (hidden comment: 885012206077)
C53  value 1nF  VDC_V: 100V  PackageReference: 0805  [CC2012-0805]  (hidden comment: 885012207116)
C54  value 100nF  VDC_V: 100V  PackageReference: 0805  [CC2012-0805]  (hidden comment: 885012207128)
C55  value 100uF  VDC_V: 16V  [SMT 6.3mmx7.7mm - WE]  (hidden comment: 865230345005)
C56  value 22uF  VDC_V: 25V  PackageReference: 1210  [CC3225-1210]  (hidden comment: 885012109014)
C57  value 1uF  VDC_V: 25V  PackageReference: 0805  [CC2012-0805]  (hidden comment: 885382207003)
C58  value 22uF  VDC_V: 25V  [SMT 5mmx5.5mm - WE]  (hidden comment: 865060442002)
C59  value 47pF  VDC_V: 50V  PackageReference: 0603  [CC1608-0603]  (hidden comment: 885012006055)
C60  value 1uF  VDC_V: 16V  PackageReference: 0603  [CC1608-0603]  (hidden comment: 885012206052)
C61  value 22nF  VDC_V: 50V  PackageReference: 0603  [CC1608-0603]  (hidden comment: 885012206091)
C62  value 10pF  PackageReference: 0603  [CC1608-0603]  (hidden comment: 885012006073)
C63  value 15nF  PackageReference: 0603  [CC1608-0603]  (hidden comment: 885012206090)
C64  value 1uF  VDC_V: 16V  PackageReference: 0805  [CC2012-0805]  (hidden comment: 885382207001)
C65  value 22nF  PackageReference: 1206  VDC_V: 630V  [CC3216-1206]  (hidden comment: 885342208014)
C71  value 4.7nF  VDC_V: 2kV  PackageReference: 1812  [CC4532-1812]  (hidden comment: 885342211008)
C72  value 4.7nF  VDC_V: 2kV  PackageReference: 1812  [CC4532-1812]  (hidden comment: 885342211008)
C73  value 2.2nF  VDC_V: 2kV  PackageReference: 1812  [CC4532-1812]  (hidden comment: 885342210002)
C74  value 2.2nF  VDC_V: 2kV  PackageReference: 1812  [CC4532-1812]  (hidden comment: 885342210002)
C75  value 2.2nF  VDC_V: 2kV  PackageReference: 1812  [CC4532-1812]  (hidden comment: 885342210002)
C76  value 1nF  PackageReference: 1206  VDC_V: 100V  [CC3216-1206]  (hidden comment: 885012208106)
C77  value 1nF  PackageReference: 1206  VDC_V: 100V  [CC3216-1206]  (hidden comment: 885012208106)
C78  value 1nF  VDC_V: 2kV  PackageReference: 1210  [CC3225-1210]  (hidden comment: 885342209009)
D15  value BAS16  [SOT-23]  (hidden comment: BAS16LT1G)
D16  value BAS16  [SOT-23]  (hidden comment: BAS16LT1G)
D17  value BAS16  [SOT-23]  (hidden comment: BAS16LT1G)
D18  value SMAJ58A  [SMA/DO-214AC]  (hidden comment: SMAJ58A-13-F)
D19  value BAS16  [SOT-23]  (hidden comment: BAS16LT1G)
D20  value BAS16  [SOT-23]  (hidden comment: BAS16LT1G)
D21  value BZX84C12  [SOT-23]  (hidden comment: BZX84C12LT1G)
D22  value BZX84C12  [SOT-23]  (hidden comment: BZX84C12LT1G)
D23  value SMAJ58A  [SMA/DO-214AC]  (hidden comment: SMAJ58A-13-F)
D24  BAV99RF  [SOT-23]
D25  value Green  [LED1608 (0603) - Green]  (hidden comment: 150060VS75020)
FB4  value 22R@100MHz  PackageReference: 0805  I DC: 6A  [CF2012-0805]  (hidden comment: 742792021)
IC4  PackageReference: HTSSOP20  [HTSSOP-20 6.5x4.4mm]  (hidden comment: TPS23754PWP-1)
IC5  PackageReference: SOP-4  [OPTO_WL-OCPT SOP-4]  (hidden comment: 140356145100)
IC6  value TL431AC  [SOT-23]  (hidden comment: TL431ACDBZR)
L1  value 3.3uH  [Inductor_WE-TPC 4828]  (hidden comment: 744043003)
L6  value 22uH  PackageReference: 1280  [Inductor_WE-PD 1280]  (hidden comment: 744770122)
L7  value 1mH  [Inductor_WE-PD 7332]  (hidden comment: 74477830)
L8  value 2x1000uH  [Inductor_WE-SL2]  (hidden comment: 744222)
L9  value 4.7uH  PackageReference: 4018  [Inductor_WE-LQS-4018]  (hidden comment: 74404042047)
R14  value 10k  PackageReference: 0603  [CR1608-0603]  (hidden comment: RC0603FR-0710KL)
R15  value 0R  PackageReference: 0603  [CR1608-0603]  (hidden comment: RC0603FR-070RL)
R16  value 2k  PackageReference: 1210  [CR3225-1210]  (hidden comment: RC1210FR-072KL)
R27  value 24k9  PackageReference: 0603  [CR1608-0603]  (hidden comment: RC0603FR-0724K9L)
R28  value 69k8  [CR1608-0603]  (hidden comment: RC0603FR-0769K8L)
R29  value 2k  PackageReference: 1210  [CR3225-1210]  (hidden comment: RC1210FR-072KL)
R30  value 80k6  [CR1608-0603]  (hidden comment: RC0603FR-0780K6L)
R31  value 63k4  [CR1608-0603]  (hidden comment: RC0603FR-0763K4L)
R32  value 10R  PackageReference: 0603  [CR1608-0603]  (hidden comment: RC0603FR-0710RL)
R33  value 63R4  PackageReference: 0805  [CR2012-0805]  (hidden comment: RC0805FR-0763R4L)
R34  value 1k  PackageReference: 0603  [CR1608-0603]  (hidden comment: RC0603FR-071KL)
R35  value 0.12R  PackageReference: 1206  [CR3216-1206]  (hidden comment: RL1206FR-070R12L)
R36  value 49R9  PackageReference: 0603  [CR1608-0603]  (hidden comment: RC0603FR-0749R9L)
R37  value 348R  PackageReference: 0603  [CR1608-0603]  (hidden comment: RC0603FR-07348RL)
R38  value 10k  PackageReference: 0603  [CR1608-0603]  (hidden comment: RC0603FR-0710KL)
R39  value 2k49  PackageReference: 0603  [CR1608-0603]  (hidden comment: RC0603FR-072K49L)
R40  value 1k5  PackageReference: 0603  [CR1608-0603]  (hidden comment: RC0603FR-071K5L)
R41  value 41k2  PackageReference: 0603  [CR1608-0603]  (hidden comment: RC0603FR-0741K2L)
R42  value 10k  PackageReference: 0603  [CR1608-0603]  (hidden comment: RC0603FR-0710KL)
R43  value 6k2  PackageReference: 0603  [CR1608-0603]  (hidden comment: RC0603JR-076K2L)
T1  value SI2325DS  [SOT-23]  (hidden comment: SI2325DS-T1-E3)
T2  750311320  [WE-FB_EP13]
T3  value MMBTA06  [SOT-23]  (hidden comment: MMBTA06LT1G)
T4  value SI4850EY  [SO-8]  (hidden comment: SI4850EY-T1-GE3)
T5  value MMBTA06  [SOT-23]  (hidden comment: MMBTA06LT1G)
T6  value SI4848DY  [SO-8]  (hidden comment: SI4848DY-T1-GE3)
T7  value SI7852DP  PackageReference: PowerPAK-SO-8  [PowerPAK SO-8]  (hidden comment: SI7852DP-T1-GE3)
TP6  (no value)  [TESTPOINT 1.5mm]
TP7  (no value)  [TESTPOINT 1.5mm]
TP8  (no value)  [TESTPOINT 1.5mm]
TP9  (no value)  [TESTPOINT 1.5mm]
TP10  (no value)  [TESTPOINT 1.5mm]
TP11  (no value)  [TESTPOINT 1.5mm]
TP12  (no value)  [TESTPOINT 1.5mm]
TP13  (no value)  [TESTPOINT 1.5mm]
TP14  (no value)  [TESTPOINT 1.5mm]
TP15  (no value)  [TESTPOINT 1.5mm]
TP16  (no value)  [TESTPOINT 1.5mm]
TP17  (no value)  [TESTPOINT 1.5mm]
TP18  (no value)  [TESTPOINT 1.5mm]
TP20  (no value)  [TESTPOINT 1.5mm]
TP21  (no value)  [TESTPOINT 1.5mm]
VR1  value 20k  [3296W]  (hidden comment: 3296W-1-203LF)
X3  value Screw Terminal / 2P  PackageReference: Pitch 3.5mm  [691214110002S]  (hidden comment: 691214110002S)
X4  value Male Header 1x2  [HDR1X2]  (hidden comment: 61300211121)

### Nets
AGND: C32.1 C34.2 C35.2 C39.2 C44.2 C45.2 C57.2 C58.2 C59.2 C60.2 C73.2 C78.1 D15.3(K) D20.1(A) D23.2(K) IC4.4(COM) IC4.8(ARTN) IC4.9(RTN) IC5.3(Emitter) L9.2 R14.2 R28.1 R30.1 R31.1 R35.1 T1.2(S) T2.5 TP15.1 TP18.1
GND: C32.2 C55.2 C56.2 C64.2 C74.2 C75.2 D21.1(A) D22.1(A) FB4.2 IC6.3(A) T4.1(S) T4.2(S) T4.3(S) T7.1(S) T7.2(S) T7.3(S) TP12.1 TP20.1 VR1.1 X3.2
SHIELD: C71.2 C72.1 C73.1 C74.1 C75.1
VDD_POE: C53.2 L8.2(L2)
VOUT: C55.1 C56.1 L6.2 R36.2 TP7.1 X3.1
VSS: C54.2 C72.2 D18.1(A) D23.1(A) IC4.10(VSS) IC4.21(PAD) L8.4(L1') R33.1
VSS_POE: C53.1 L8.1(L1)
T2P: D25.1 IC4.20(T2P) TP21.1
VC: C57.1 C58.1 IC4.6(VC) L7.1 TP8.1 X4.1
NetC2_1: C2.1 C65.1 T1.3(D)
NetC2_2: C2.2 C65.2 C76.1 T2.2 T6.5(D) T6.6(D) T6.7(D) T6.8(D) TP9.1
NetC33_1: C33.1 D15.1(A) R14.1 T1.1(G)
NetC33_2: C33.2 R15.2
NetC34_1: C34.1 C35.1 C39.1 C44.1 C54.1 C71.1 D18.2(K) IC4.11(VDD1) IC4.12(VDD) L1.1 L8.3(L2') R27.1
NetC45_1: C45.1 L1.2 T2.1 TP6.1
NetC52_1: C52.1 D21.3(K) R16.2 T3.1(B)
NetC52_2: C52.2 D16.3(K) L6.1 R16.1 T2.6 T2.7 T3.3(C) T4.5(D) T4.6(D) T4.7(D) T4.8(D)
NetC59_1: C59.1 IC4.3(CS) R34.1
NetC60_1: C60.1 IC4.2(VB) R37.1 R40.1 TP14.1
NetC61_1: C61.1 R37.2
NetC61_2: C61.2 IC4.1(CTL) IC5.4(Collector) R40.2 TP17.1
NetC62_1: C62.1 D24.1(A) IC5.2(Cathode) IC6.1(K) R42.1
NetC62_2: C62.2 C63.2 IC6.2(REF) R41.2 VR1.2 VR1.3
NetC63_1: C63.1 R42.2
NetC64_1: C64.1 D24.3(COM) R38.2
NetC76_2: C76.2 C77.1
NetC77_2: C77.2 L9.1
NetC78_2: C78.2 FB4.1
NetD16_1: D16.1(A) T3.2(E) T7.4(G)
NetD17_1: D17.1(A) T4.4(G) T5.2(E)
NetD17_3: D17.3(K) R29.1 T2.9 T2.10 T5.3(C) T7.5(D) T7.6(D) T7.7(D) T7.8(D)
NetD19_1: D19.1(A) T2.4
NetD19_3: D19.3(K) D20.3(K) L7.2
NetD22_3: D22.3(K) R29.2 T5.1(B)
NetD24_2: D24.2(K) R36.1 R38.1 R39.2 R41.1 TP16.1
NetD25_2: D25.2 R43.1
NetIC4_5: IC4.5(GATE) R32.1 TP11.1
NetIC4_7: IC4.7(GAT2) R15.1 TP10.1
NetIC4_13: IC4.13(DEN) R27.2
NetIC4_15: IC4.15(CLS) R33.2
NetIC4_16: IC4.16(DT) R31.2
NetIC4_18: IC4.18(BLNK) R30.2
NetIC4_19: IC4.19(FRS) R28.2
NetIC5_1: IC5.1(Anode) R39.1
NetR32_2: R32.2 T6.4(G)
NetR34_2: R34.2 R35.2 T6.1(S) T6.2(S) T6.3(S) TP13.1
NetR43_2: R43.2 X4.2

Not connected (* = marked no-connect by the designer): IC4 14(NC)* 17(APD)*

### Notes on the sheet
- Type 2 PSE indicator
- Rev.
- Content
- Date
- Name
- WÜRTH Elektronik eiSos
- Customer:
- Print Date :
- Size
- A3
- Document Number
- Design Date :
- Modified By:
- Sheet:
- of
- Rev

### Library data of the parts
C2 C65 = 885342208014: CAP, CERM, 22nF, 630V, +/-10%, X7R, 1206; Manufacturer: Wurth; Polarized: N; TaMax_C: 125; TaMin_C: -55; Tolerance_%: 10; CompType: Capacitor
C32 C73-C75 = 885342210002: CAP, CERM, 2.2nF, 2kV, +/-10%, X7R, 1812; Manufacturer: Wurth; Polarized: N; TaMax_C: 125; TaMin_C: -55; Tolerance_%: 10; CompType: Capacitor
C33 C60 = 885012206052: as C9 on sheet 01-USB_C
C34 C54 = 885012207128: CAP, CERM, 100nF, 100V, +/-10%, X7R, 0805; Manufacturer: Wurth; Polarized: N; TaMax_C: 125; TaMin_C: -55; Tolerance_%: 10; CompType: Capacitor
C35 C45 = 885012209069: CAP, CERM, 1uF, 100V, +/-10%, X7R, 1210; Manufacturer: Wurth; Polarized: N; TaMax_C: 125; TaMin_C: -55; Tolerance_%: 10%; CompType: Capacitor
C39 C44 = 865080853006: CAP, ECAP, 22uF, 100V, +/-20%, 8mm x 10.5mm; Manufacturer: Wurth; Polarized: Y; TaMax_C: 105; TaMin_C: -55; Tolerance_%: 20; CompType: Capacitor
C52 = 885012206077: CAP, CERM, 100pF, 50V, +/-10%, X7R, 0603; Manufacturer: Wurth; Polarized: N; TaMax_C: 125; TaMin_C: -55; Tolerance_%: 1; CompType: Capacitor
C53 = 885012207116: CAP, CERM, 1nF, 100V, +/-10%, X7R, 0805; Manufacturer: Wurth; Polarized: N; TaMax_C: 125; TaMin_C: -55; Tolerance_%: 10; CompType: Capacitor
C55 = 865230345005: CAP, ECAP, 100uF, 16V, +/-20%, 6.3mm x 7.7mm; Manufacturer: Wurth; ESR_Ohm: -Ohm; IRMS_A: 0.081A; Polarized: Y; TaMax_C: 105; TaMin_C: -40; Tolerance_%: 20; CompType: Capacitor
C56 = 885012109014: CAP, CERM, 22uF, 25V, +/-20%, X5R, 1210; Manufacturer: Wurth; Polarized: N; TaMax_C: 85; TaMin_C: -55; Tolerance_%: 20%; CompType: Capacitor
C57 = 885382207003: CAP, CERM, 1uF, 25V, +/-10%, X7R, 0805; Manufacturer: Wurth; Polarized: N; TaMax_C: 125; TaMin_C: -55; Tolerance_%: 10; CompType: Capacitor
C58 = 865060442002: CAP, ECAP, 22uF, 25V, +/-20%, 5mm x 5.5mm; Manufacturer: Wurth; ESR_Ohm: -Ohm; IRMS_A: 0.15A; Polarized: Y; TaMax_C: 105; TaMin_C: -55; Tolerance_%: 20; CompType: Capacitor
C59 = 885012006055: CAP, CERM, 47pF, 50V, +/-5%, C0G, 0603; Manufacturer: Wurth; Polarized: N; TaMax_C: 125; TaMin_C: -55; Tolerance_%: 5%; CompType: Capacitor
C61 = 885012206091: CAP, CERM, 22nF, 50V, +/-10%, X7R, 0603; Manufacturer: Wurth; Polarized: N; TaMax_C: 125; TaMin_C: -55; Tolerance_%: 10%; CompType: Capacitor
C62 = 885012006073: CAP, CERM, 10pF, 100V, +/-5%, C0G, 0603; Manufacturer: Wurth; Polarized: N; TaMax_C: 125; TaMin_C: -55; Tolerance_%: 5; CompType: Capacitor
C63 = 885012206090: CAP, CERM, 15nF, 50V, +/-10%, X7R, 0603; Manufacturer: Wurth; Polarized: N; TaMax_C: 125; TaMin_C: -55; Tolerance_%: 10%; CompType: Capacitor
C64 = 885382207001: CAP, CERM, 1uF, 16V, +/-10%, X7R, 0805; Manufacturer: Wurth; Polarized: N; TaMax_C: 125; TaMin_C: -55; Tolerance_%: 10; CompType: Capacitor
C71 C72 = 885342211008: CAP, CERM, 4.7nF, 2kV, +/-10%, X7R, 1812; Manufacturer: Wurth; Polarized: N; TaMax_C: 125; TaMin_C: -55; Tolerance_%: 10; CompType: Capacitor
C76 C77 = 885012208106: CAP, CERM, 1nF, 100V, +/-10%, X7R, 1206; Manufacturer: Wurth; Polarized: N; TaMax_C: 125; TaMin_C: -55; Tolerance_%: 10; CompType: Capacitor
C78 = 885342209009: as C1 on sheet 01-USB_C
D15-D17 D19 D20 = BAS16LT1G: DIODE, Switching, 75V, 0.2A, SOT-23; Manufacturer: Onsemi
D18 D23 = SMAJ58A-13-F: DIODE, TVS , 58V, 400W, Unidirection, SMA; Manufacturer: Diodes
D21 D22 = BZX84C12LT1G: DIODE, ZENER, 12V, 300mW, SOT-23; Manufacturer: Diodes
D24 = BAV99 RF: DIODE, Dual, 70V, 0.2A, SOT-23; Manufacturer: Taiwan Semi
D25 = 150060VS75020: as D5 on sheet 01-USB_C
FB4 = 742792021: Ferrite Bead 22R @ 100MHz / 0805 / 6.0A; Manufacturer: Wurth
IC4 = TPS23754PWP-1: IC IEEE 802.3at POE/DC-DC, HTSSOP20; Manufacturer: TI
IC5 = 140356145100: OPTOISOLATOR, 3.75kV, 50mA, SOP-4; Manufacturer: Wurth
IC6 = TL431ACDBZR: IC VREF SERIES 2.495V; Manufacturer: TI
L1 = 744043003: Inductor 3.3uH / 4828 / 2.15A; Manufacturer: Wurth
L6 = 744770122: Inductor 22uH / 1280 / 4.1A; Manufacturer: Wurth
L7 = 74477830: Inductor 1mH / 7332 / 0.2A; Manufacturer: Wurth
L8 = 744222: Common Mode Chokes 2x1000uH / 9.2x6mm / 800mA; Manufacturer: Wurth; Rdc: 0.207; I DC: 0.8A
L9 = 74404042047: Inductor 4.7uH / 4018 / 1.7A; Manufacturer: Wurth
R14 R38 R42 = RC0603FR-0710KL: as R5 on sheet 01-USB_C
R15 = RC0603FR-070RL: RES, 0 ohm, 1%, 0.1W, 0603; Manufacturer: Yageo; CompType: Resistor; Power_W: 0.1
R16 R29 = RC1210FR-072KL: RES, 2k ohm, 1%, 0.5W, 1210; Manufacturer: YAGEO; CompType: Resistor; Tolerance_%: 1
R27 = RC0603FR-0724K9L: RES, 24.9kohm, 1%, 0.1W, 0603; Manufacturer: Yageo; CompType: Resistor; Power_W: 0.1
R28 = RC0603FR-0769K8L: RES, 69.8kohm, 1%, 0.1W, 0603; Manufacturer: Yageo; CompType: Resistor; Power_W: 0.1
R30 = RC0603FR-0780K6L: RES, 80.6kohm, 1%, 0.1W, 0603; Manufacturer: Yageo; CompType: Resistor; Power_W: 0.1
R31 = RC0603FR-0763K4L: RES, 63.4kohm, 1%, 0.1W, 0603; Manufacturer: Yageo; CompType: Resistor; Power_W: 0.1
R32 = RC0603FR-0710RL: RES, 10 ohm, 1%, 0.1W, 0603; Manufacturer: Yageo; CompType: Resistor; Power_W: 0.1
R33 = RC0805FR-0763R4L: RES, 63.4 ohm, 1%, 0.125W, 0805; Manufacturer: Yageo; CompType: Resistor; Power_W: 0.125
R34 = RC0603FR-071KL: RES, 1kohm, 1%, 0.1W, 0603; Manufacturer: Yageo; CompType: Resistor; Power_W: 0.1
R35 = RL1206FR-070R12L: RES, 0.12 ohm, 1%, 1W, 1206; Manufacturer: YAGEO; CompType: Resistor; Power_W: 1
R36 = RC0603FR-0749R9L: RES, 49.9 ohm, 1%, 0.1W, 0603; Manufacturer: Yageo; CompType: Resistor; Power_W: 0.1
R37 = RC0603FR-07348RL: RES, 348 ohm, 1%, 0.1W, 0603; Manufacturer: Yageo; CompType: Resistor; Power_W: 0.1
R39 = RC0603FR-072K49L: RES, 2.49kohm, 1%, 0.1W, 0603; Manufacturer: Yageo; CompType: Resistor; Power_W: 0.1
R40 = RC0603FR-071K5L: RES, 1.5kohm, 1%, 0.1W, 0603; Manufacturer: Yageo; CompType: Resistor; Power_W: 0.1
R41 = RC0603FR-0741K2L: RES, 41.2kohm, 1%, 0.1W, 0603; Manufacturer: Yageo; CompType: Resistor; Power_W: 0.1
R43 = RC0603JR-076K2L: RES, 6.2kohm, 1%, 0.1W, 0603; Manufacturer: Yageo; CompType: Resistor; Power_W: 0.1
T1 = SI2325DS-T1-E3: MOSFET, P-CH, 20V, 0.69A, SOT-23; Manufacturer: Vishay
T2 = 750311320: Trans, POE, 30W, SMT; Manufacturer: Wurth; CompType: Transformer
T3 T5 = MMBTA06LT1G: Transistor, NPN, 80V, 0.5A, SOT-23; Manufacturer: Onsemi
T4 = SI4850EY-T1-GE3: MOSFET, N-CH, 60V, 8.5A, SO-8; Manufacturer: Vishay
T6 = SI4848DY-T1-GE3: MOSFET, N-CH, 150V, 3.7A, SO-8; Manufacturer: Vishay
T7 = SI7852DP-T1-GE3: MOSFET, N-CH, 80V, 12.5A, PowerPAK-SO-8; Manufacturer: Vishay
TP6-TP18 TP20 TP21 = TP / 1.5mm: Test Point, SMT, Miniature; Value: 1.5mm
VR1 = 3296W-1-203LF: Trimmer, 20kohm, 10%, 0.5W, 4.83x9.53x10.03mm; Manufacturer: Bourns; Power_W: 0.5
X3 = 691214110002S: CON, Terminal Block, Screw, 2P, P3.5mm, 10A, INS; Manufacturer: Wurth; CompType: Connector
X4 = 61300211121: CON, Header, Male, 2P, P2.54mm, Straight, INS; Manufacturer: Wurth; CompType: Connector

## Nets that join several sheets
GND: 01-USB_C (64 pins), 02-POE (20 pins)
SHIELD: 01-USB_C (21 pins), 02-POE (5 pins)
VDD_POE: 01-USB_C (D1.2 D8.2 D9.2 D10.2), 02-POE (C53.2 L8.2)
VOUT: 01-USB_C (C25.2 C28.1 IC2.1), 02-POE (6 pins)
VSS_POE: 01-USB_C (D11.1 D12.1 D13.1 D14.1), 02-POE (C53.1 L8.1)

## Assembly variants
Variant of Prototype: not fitted C36 C41 C46 C47 C48 C49 C50 C51 C75 R8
